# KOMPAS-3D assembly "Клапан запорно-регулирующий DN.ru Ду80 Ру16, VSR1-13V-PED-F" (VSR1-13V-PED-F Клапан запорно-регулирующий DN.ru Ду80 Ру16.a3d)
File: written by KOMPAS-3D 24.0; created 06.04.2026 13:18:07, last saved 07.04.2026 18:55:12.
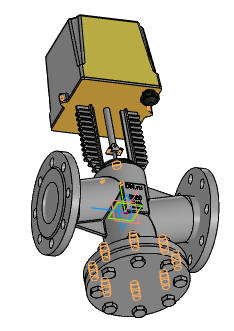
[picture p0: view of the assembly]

Document properties: Автор: R2D2; Полное имя файла: E:\Работа\Зайцев\Солянка\VSR1-13V-PED-F Клапан запорно-регулирующий DN.ru\DN80\исходные материалы\VSR1-13V-PED-F Клапан запорно-регулирующий DN.ru Ду80 Ру16.a3d

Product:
- Component [detail]: Фланец  | qty 2  | pos. 1  | Масса: 3.445383; Автор: R2D2; source file: Фланец.m3d
- Component [detail]: Фланец  | qty 1  | pos. 2  | Масса: 3.445383; Автор: R2D2; source file: Фланец.m3d
- Component [detail]: Корпус  | qty 1  | pos. 3  | Масса: 6.9; Автор: R2D2; source file: Корпус.m3d
- Component [detail]: Электропривод  | qty 1  | pos. 6  | Масса: 0.101125; Автор: R2D2; source file: Электропривод.m3d
- Component [standard]: Болт с шестигранной головкой ГОСТ Р ИСО 4014 - М16 x 65  | qty 8  | Материал: Не определено (density 1000 kg/m3); Масса: 0.1404; Раздел спецификации: Стандартные изделия; Рассекать на разрезах: no; additional columns: ГОСТ Р ИСО 4014-2013
- Component [standard]: Гайка М16-6H ГОСТ 5915-70  | qty 8  | Масса: 0.03761; Раздел спецификации: Стандартные изделия; Рассекать на разрезах: no; additional columns: М1,6-6H
- Part/product: Клапан запорно-регулирующий DN.ru Ду80 Ру16  | designation VSR1-13V-PED-F
    Масса: 27.5
    Раздел спецификации: Прочие изделия
    Примечание: D090-02893

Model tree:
1. Эскиз:1
2. Ось конической поверхности:19
3. Смещенная плоскость:19
4. ЛСК:19  (with: Плоскость XY, Плоскость ZX, Плоскость ZY, Ось X, Ось Y, Ось Z)
     Ось X. Y = -1; Ось Y. X = 1; Ось Z. Z = 1; Точка начала. Х = -30.6147; Точка начала. Z = -73.9104
5. Болтовое соединение
6. Массив по концентрической сетке:3  (with: Грань.Элемент выдавливания:1, Грань.Элемент вращения:1, Грань.Элемент выдавливания:8)  (8 pattern instances)
     Шаг 2 = 360; Ориентация = 2; Расстояние = -40

Expressions: VSR1-13V-PED-F; -L/2
Referenced files in E:\Работа\Зайцев\Солянка\VSR1-13V-PED-F Клапан запорно-регулирующий DN.ru\DN80\исходные материалы\: Фланец.m3d, Корпус.m3d, Электропривод.m3d
Referenced files in C:\Program Files\ASCON\KOMPAS-3D v24\Libs\PolynomLib\DATA\vault\Methods\Kompas\3D\: PLib_Bolt_1_ISO_1100.m3d, PLib_Nut_OST92_900.m3d
Referenced files in E:\Работа\Зайцев\Солянка\VSR1-13V-PED-F Клапан запорно-регулирующий DN.ru\DN20\исходные материалы\: Фланец.m3d
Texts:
  Болт с шестигранной головкой
  Крепежное изделие ГОСТ
  Программные изделия  и базы данных
  Edge1
  Edge2
  TKR3D
  Справочник стандартных изделий
  Фланец (1)
  Фланец (2)
  Фланец (3)
  Болт с шестигранной головкой ГОСТ Р ИСО 4014 - М16 x 65 (1)
  hole1
  hole2
  Гайка М16-6H ГОСТ 5915-70 (1)
  bcut1
  hcut1
  cut1
  Болт с шестигранной головкой ГОСТ Р ИСО 4014 - М16 x 65 (2)
  Гайка М16-6H ГОСТ 5915-70 (2)
  Болт с шестигранной головкой ГОСТ Р ИСО 4014 - М16 x 65 (3)
  Гайка М16-6H ГОСТ 5915-70 (3)
  Болт с шестигранной головкой ГОСТ Р ИСО 4014 - М16 x 65 (4)
  Гайка М16-6H ГОСТ 5915-70 (4)
  Болт с шестигранной головкой ГОСТ Р ИСО 4014 - М16 x 65 (5)
  Гайка М16-6H ГОСТ 5915-70 (5)
  Болт с шестигранной головкой ГОСТ Р ИСО 4014 - М16 x 65 (6)
  Гайка М16-6H ГОСТ 5915-70 (6)
  Болт с шестигранной головкой ГОСТ Р ИСО 4014 - М16 x 65 (7)
  Гайка М16-6H ГОСТ 5915-70 (7)
  Болт с шестигранной головкой ГОСТ Р ИСО 4014 - М16 x 65 (8)
  Гайка М16-6H ГОСТ 5915-70 (8)
  Плоскость XY.Начало координат
  Ось Z.Начало координат
  Плоскость ZY.Начало координат
  Плоскость ZX.Начало координат
  Ось Y.Начало координат
  Plane. Начало координат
